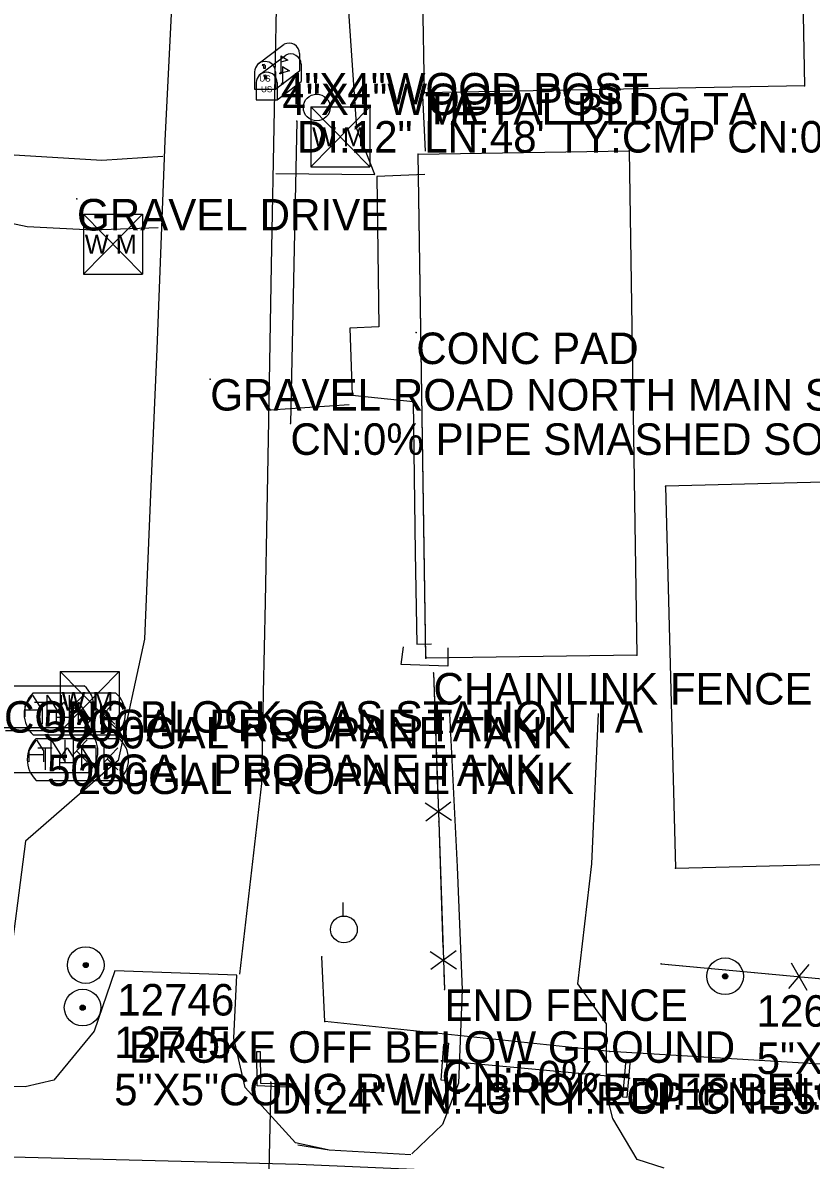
# Model space of a CAD drawing. Extents: x 1050807 to 1053552, y 395828 to 398415.
# Drawn here: x 1051611.7 to 1051736.8, y 398091.9 to 398272.3 of the extents above; entities that cross this region are included whole.
import ezdxf

# ---------------------------------------------------------------- set-up
doc = ezdxf.new("R2010")
doc.units = 0
for name, color, linetype in [('S_BUILDING', 7, 'Continuous'), ('S_BUILDING_ANNOT', 7, 'Continuous'), ('S_CROSS_DRAIN', 7, 'Continuous'), ('S_CROSS_DRAIN_ANNOT', 7, 'Continuous'), ('S_DRG_PT_SYM', 7, 'Continuous'), ('S_DRIVEWAY', 7, 'Continuous'), ('S_EDGE_CONCRETE', 7, 'Continuous'), ('S_EDGE_PAVEMENT', 7, 'Continuous'), ('S_FENCE', 7, 'Continuous'), ('S_FENCE_ANNOT', 7, 'Continuous'), ('S_GRAVEL_ROAD', 7, 'Continuous'), ('S_HEADWALL', 7, 'Continuous'), ('S_IRON_PIN', 7, 'Continuous'), ('S_IRON_PIN_ANNOT', 7, 'Continuous'), ('S_MAILBOX', 7, 'Continuous'), ('S_MAILBOX_ANNOT', 7, 'Continuous'), ('S_MSC_PT_SYM', 7, 'Continuous'), ('S_SHOULDER', 7, 'Continuous'), ('S_STR_PT_SYM', 7, 'Continuous'), ('S_SURVEY_TEXT_ANNOT', 7, 'Continuous'), ('S_TANK', 7, 'Continuous'), ('S_TANK_ANNOT', 7, 'Continuous'), ('S_UTILITY_POLE', 7, 'Continuous'), ('S_UTL_PT_SYM', 7, 'Continuous'), ('S_WATER_UTILITIES', 7, 'Continuous')]:
    doc.layers.add(name, color=color, linetype=linetype)

msp = doc.modelspace()

# ---------------------------------------------------------------- linework, layer by layer
at = {"layer": 'S_BUILDING'}
for p, q in [((1051734.78, 398312.8), (1051735.73, 398262.3)), ((1051675.44, 398261.14), (1051674.48, 398311.66)), ((1051675.44, 398261.16), (1051674.48, 398311.66)), ((1051735.73, 398262.3), (1051675.44, 398261.16)), ((1051674.4, 398251.46), (1051707.9, 398251.97)), ((1051675.63, 398171.71), (1051674.4, 398251.46)), ((1051675.63, 398171.47), (1051674.4, 398251.46)), ((1051707.9, 398251.97), (1051709.13, 398171.98)), ((1051754.28, 398199.8), (1051713.69, 398198.75)), ((1051713.69, 398198.75), (1051715.26, 398138.16)), ((1051709.13, 398171.98), (1051675.63, 398171.47)), ((1051715.26, 398138.16), (1051775.84, 398139.73))]:
    msp.add_line(p, q, dxfattribs=at)
at = {"layer": 'S_CROSS_DRAIN'}
for p, q in [((1051655.17, 398256.69), (1051654.14, 398208.74)), ((1051707.99, 398104.89), (1051678.15, 398107.62)), ((1051651.04, 398104.23), (1051650.09, 398061.31))]:
    msp.add_line(p, q, dxfattribs=at)
at = {"layer": 'S_DRG_PT_SYM'}
for points in [[(1051655.17, 398256.69), (1051655.17, 398256.74), (1051655.17, 398256.69), (1051655.12, 398256.69), (1051655.17, 398256.69), (1051655.17, 398256.64), (1051655.17, 398256.69), (1051655.22, 398256.69)], [(1051654.14, 398208.74), (1051654.14, 398208.79), (1051654.14, 398208.74), (1051654.09, 398208.74), (1051654.14, 398208.74), (1051654.14, 398208.69), (1051654.14, 398208.74), (1051654.19, 398208.74)], [(1051678.15, 398107.62), (1051678.15, 398107.67), (1051678.15, 398107.62), (1051678.1, 398107.62), (1051678.15, 398107.62), (1051678.15, 398107.57), (1051678.15, 398107.62), (1051678.2, 398107.62)], [(1051651.04, 398104.23), (1051651.04, 398104.28), (1051651.04, 398104.23), (1051650.99, 398104.23), (1051651.04, 398104.23), (1051651.04, 398104.18), (1051651.04, 398104.23), (1051651.09, 398104.23)], [(1051707.99, 398104.89), (1051707.99, 398104.94), (1051707.99, 398104.89), (1051707.94, 398104.89), (1051707.99, 398104.89), (1051707.99, 398104.84), (1051707.99, 398104.89), (1051708.04, 398104.89)]]:
    msp.add_lwpolyline(points, dxfattribs=at)
at = {"layer": 'S_DRIVEWAY'}
for points in [[(1051633.9, 398251.06), (1051624.2, 398250.45), (1051611.13, 398251.24), (1051598.06, 398252.03)], [(1051600.84, 398242.41), (1051612.38, 398239.95), (1051622.75, 398239.41), (1051633.14, 398239.78)]]:
    msp.add_lwpolyline(points, dxfattribs=at)
at = {"layer": 'S_EDGE_CONCRETE'}
for points in [[(1051675.5, 398248.23), (1051667.87, 398247.87), (1051668.16, 398224.07), (1051663.57, 398223.86), (1051663.97, 398213.21), (1051673.61, 398212.18), (1051673.95, 398188.26), (1051674.19, 398173.7), (1051676.55, 398173.76)], [(1051679.11, 398173.15), (1051679.15, 398170.23), (1051671.75, 398170.51), (1051672.12, 398173.28)]]:
    msp.add_lwpolyline(points, dxfattribs=at)
at = {"layer": 'S_EDGE_PAVEMENT'}
for points in [[(1051679.39, 398162.7), (1051680.64, 398138.4), (1051681.41, 398118.88), (1051680.81, 398104.07), (1051678.3, 398097.51), (1051673.44, 398092.89)], [(1051713.48, 398090.6), (1051709.19, 398091.98), (1051705.31, 398098.47), (1051704.3, 398102.36), (1051704.31, 398113.47), (1051699.76, 398119.86), (1051701.99, 398138.89), (1051703.06, 398162.71)], [(1051660.07, 398093.51), (1051654.98, 398094.64), (1051646.94, 398103.37), (1051645.14, 398111.23), (1051645.64, 398121.2), (1051626.27, 398121.92), (1051623.02, 398112.31), (1051616.62, 398104.54), (1051612.06, 398103.47), (1051594.68, 398103.64), (1051577.3, 398103.81), (1051557.13, 398104.42)], [(1051831.93, 398069.76), (1051807.96, 398075.33), (1051783.99, 398080.9), (1051771.44, 398082.45), (1051758.89, 398083.99), (1051746.34, 398085.53), (1051733.79, 398087.07), (1051716.6, 398088.19), (1051699.41, 398089.32), (1051677.43, 398090.24), (1051655.45, 398091.16), (1051630.63, 398091.8), (1051605.81, 398092.43), (1051581.35, 398093.1), (1051556.88, 398093.77)]]:
    msp.add_lwpolyline(points, dxfattribs=at)
at = {"layer": 'S_FENCE'}
for p, q in [((1051676.85, 398169.14), (1051677.68, 398145.54)), ((1051675.53, 398148.53), (1051679.72, 398145.8)), ((1051675.53, 398148.53), (1051679.72, 398145.8)), ((1051679.62, 398148.67), (1051675.63, 398145.66)), ((1051679.62, 398148.67), (1051675.63, 398145.66)), ((1051677.68, 398145.54), (1051678.59, 398118.96)), ((1051676.34, 398124.95), (1051680.53, 398122.23)), ((1051676.34, 398124.95), (1051680.53, 398122.23)), ((1051680.43, 398125.09), (1051676.43, 398122.09)), ((1051680.43, 398125.09), (1051676.43, 398122.09)), ((1051712.99, 398123.01), (1051762.29, 398118.45)), ((1051733.65, 398123.15), (1051736.13, 398118.81)), ((1051733.65, 398123.15), (1051736.13, 398118.81)), ((1051733.28, 398119.07), (1051736.51, 398122.89)), ((1051733.28, 398119.07), (1051736.51, 398122.89))]:
    msp.add_line(p, q, dxfattribs=at)
for points in [[(1051676.85, 398169.14), (1051677.55, 398149.16)], [(1051676.85, 398169.14), (1051677.55, 398149.16)], [(1051677.68, 398145.54), (1051678.36, 398125.59)], [(1051677.68, 398145.54), (1051678.36, 398125.59)], [(1051712.99, 398123.01), (1051732.9, 398121.17)], [(1051712.99, 398123.01), (1051732.9, 398121.17)], [(1051678.5, 398121.6), (1051678.59, 398118.96)], [(1051678.5, 398121.6), (1051678.59, 398118.96)]]:
    msp.add_lwpolyline(points, dxfattribs=at)
at = {"layer": 'S_GRAVEL_ROAD'}
for points in [[(1051646.11, 398121.35), (1051647.87, 398136.49), (1051649.63, 398151.62), (1051649.9, 398166.01), (1051650.17, 398180.39), (1051650.44, 398194.78), (1051650.71, 398209.17), (1051651.17, 398233.83), (1051651.63, 398258.49), (1051652.11, 398282.74), (1051652.58, 398307), (1051652.86, 398330.58), (1051653.15, 398354.17), (1051652.43, 398372.13), (1051651.71, 398390.09)], [(1051596, 398378.84), (1051614.53, 398374.86), (1051630.13, 398364.4), (1051635.87, 398350.62), (1051635.97, 398336.92), (1051636.08, 398323.21), (1051636.19, 398309.51), (1051636.29, 398295.81), (1051635.27, 398274.7), (1051634.24, 398253.59), (1051633.6, 398237.04), (1051632.96, 398220.48), (1051631.96, 398197.51), (1051630.97, 398174.53), (1051626.82, 398155.24), (1051612.08, 398142.48), (1051609.17, 398119.93), (1051608.83, 398103.64)], [(1051651.83, 398248.35), (1051667.57, 398248.22), (1051664.68, 398255.48), (1051663.69, 398270.22), (1051662.7, 398284.95), (1051663.01, 398308.7), (1051661.12, 398315.25), (1051655.29, 398310.44), (1051652.69, 398306.96)], [(1051675.09, 398260.74), (1051675.56, 398251.91)], [(1051663.48, 398211.65), (1051650.98, 398210.85)]]:
    msp.add_lwpolyline(points, dxfattribs=at)
at = {"layer": 'S_HEADWALL'}
for points in [[(1051678.59, 398110.46), (1051679.23, 398110.44), (1051678.71, 398104.52), (1051678.08, 398104.58), (1051678.48, 398110.26)], [(1051654.95, 398104.01), (1051654.88, 398103.41), (1051648.86, 398103.66), (1051648.84, 398109.11), (1051649.37, 398109.11), (1051649.42, 398104.1), (1051654.79, 398103.96)], [(1051707.52, 398101.81), (1051706.93, 398101.87), (1051707.42, 398107.81), (1051708.07, 398107.76), (1051707.54, 398101.81)]]:
    msp.add_lwpolyline(points, dxfattribs=at)
at = {"layer": 'S_IRON_PIN'}
for centre, radius in [((1051621.66, 398122.81), 2.91), ((1051621.66, 398122.81), 0.411), ((1051621.66, 398122.81), 0.262), ((1051621.66, 398122.81), 0.212), ((1051723.14, 398121.03), 2.91), ((1051621.66, 398122.81), 0.145), ((1051621.66, 398122.81), 0.0822), ((1051621.66, 398122.81), 0.0581), ((1051723.14, 398121.03), 0.411), ((1051723.14, 398121.03), 0.262), ((1051723.14, 398121.03), 0.212), ((1051723.14, 398121.03), 0.145), ((1051723.14, 398121.03), 0.0822), ((1051723.14, 398121.03), 0.0581), ((1051621.17, 398116.06), 2.91), ((1051621.17, 398116.06), 0.411), ((1051621.17, 398116.06), 0.262), ((1051621.17, 398116.06), 0.212), ((1051621.17, 398116.06), 0.145), ((1051621.17, 398116.06), 0.0822), ((1051621.17, 398116.06), 0.0581)]:
    msp.add_circle(centre, radius, dxfattribs=at)
at = {"layer": 'S_MAILBOX'}
for p, q in [((1051649.01, 398265.75), (1051653.15, 398268.86)), ((1051655.58, 398267.39), (1051655.58, 398264.67)), ((1051649.27, 398264.05), (1051653.4, 398267.16)), ((1051652.63, 398267.04), (1051652.63, 398264.32)), ((1051655.83, 398265.69), (1051655.83, 398262.97)), ((1051648.46, 398264.48), (1051648.46, 398261.76)), ((1051651.78, 398261.76), (1051655.58, 398264.67)), ((1051651.78, 398264.48), (1051651.78, 398261.76)), ((1051652.88, 398265.34), (1051652.88, 398262.63)), ((1051648.71, 398262.78), (1051648.71, 398260.07)), ((1051652.04, 398260.07), (1051655.83, 398262.97)), ((1051652.04, 398262.78), (1051652.04, 398260.07)), ((1051648.46, 398261.76), (1051651.78, 398261.76)), ((1051648.71, 398260.07), (1051652.04, 398260.07))]:
    msp.add_line(p, q, dxfattribs=at)
for points in [[(1051649.64, 398265.59), (1051649.87, 398265.45), (1051649.87, 398265.07), (1051650.17, 398265.07), (1051650.17, 398265.43), (1051649.98, 398265.67), (1051649.64, 398265.62)], [(1051652.63, 398267.04), (1051653.74, 398266.37), (1051652.63, 398266.03)], [(1051649.9, 398263.9), (1051650.12, 398263.76), (1051650.12, 398263.37), (1051650.42, 398263.37), (1051650.42, 398263.73), (1051650.23, 398263.98), (1051649.9, 398263.92)], [(1051652.88, 398265.34), (1051653.99, 398264.68), (1051652.88, 398264.33)]]:
    msp.add_lwpolyline(points, dxfattribs=at)
for centre, end in [((1051653.92, 398267.39), 117.5718), ((1051654.17, 398265.69), 117.5718), ((1051650.12, 398264.48), 180), ((1051650.38, 398262.78), 180)]:
    msp.add_arc(centre, 1.66, 0, end, dxfattribs=at)
for centre in [(1051652.63, 398264.32), (1051652.88, 398262.63)]:
    msp.add_ellipse(centre, major_axis=(0.145, 0.132), ratio=0.564646, dxfattribs=at)
at = {"layer": 'S_MSC_PT_SYM'}
for points in [[(1051620.27, 398244.33), (1051620.27, 398244.38), (1051620.27, 398244.33), (1051620.22, 398244.33), (1051620.27, 398244.33), (1051620.27, 398244.28), (1051620.27, 398244.33), (1051620.32, 398244.33)], [(1051674.13, 398223.14), (1051674.13, 398223.19), (1051674.13, 398223.14), (1051674.08, 398223.14), (1051674.13, 398223.14), (1051674.13, 398223.09), (1051674.13, 398223.14), (1051674.18, 398223.14)], [(1051641.42, 398215.77), (1051641.42, 398215.82), (1051641.42, 398215.77), (1051641.37, 398215.77), (1051641.42, 398215.77), (1051641.42, 398215.72), (1051641.42, 398215.77), (1051641.47, 398215.77)], [(1051676.85, 398169.14), (1051676.85, 398169.19), (1051676.85, 398169.14), (1051676.8, 398169.14), (1051676.85, 398169.14), (1051676.85, 398169.09), (1051676.85, 398169.14), (1051676.9, 398169.14)], [(1051677.68, 398145.54), (1051677.68, 398145.59), (1051677.68, 398145.54), (1051677.63, 398145.54), (1051677.68, 398145.54), (1051677.68, 398145.49), (1051677.68, 398145.54), (1051677.73, 398145.54)], [(1051712.99, 398123.01), (1051712.99, 398123.06), (1051712.99, 398123.01), (1051712.94, 398123.01), (1051712.99, 398123.01), (1051712.99, 398122.96), (1051712.99, 398123.01), (1051713.04, 398123.01)], [(1051678.59, 398118.96), (1051678.59, 398119.01), (1051678.59, 398118.96), (1051678.54, 398118.96), (1051678.59, 398118.96), (1051678.59, 398118.91), (1051678.59, 398118.96), (1051678.64, 398118.96)]]:
    msp.add_lwpolyline(points, dxfattribs=at)
at = {"layer": 'S_SHOULDER'}
msp.add_lwpolyline([(1051673.26, 398092.7), (1051660.28, 398093.46), (1051655.32, 398094.22)], dxfattribs=at)
at = {"layer": 'S_STR_PT_SYM'}
for points in [[(1051735.73, 398262.3), (1051735.73, 398262.35), (1051735.73, 398262.3), (1051735.68, 398262.3), (1051735.73, 398262.3), (1051735.73, 398262.25), (1051735.73, 398262.3), (1051735.78, 398262.3)], [(1051675.44, 398261.16), (1051675.44, 398261.21), (1051675.44, 398261.16), (1051675.39, 398261.16), (1051675.44, 398261.16), (1051675.44, 398261.11), (1051675.44, 398261.16), (1051675.49, 398261.16)], [(1051675.44, 398261.14), (1051675.44, 398261.19), (1051675.44, 398261.14), (1051675.39, 398261.14), (1051675.44, 398261.14), (1051675.44, 398261.09), (1051675.44, 398261.14), (1051675.49, 398261.14)], [(1051674.4, 398251.46), (1051674.4, 398251.51), (1051674.4, 398251.46), (1051674.35, 398251.46), (1051674.4, 398251.46), (1051674.4, 398251.41), (1051674.4, 398251.46), (1051674.45, 398251.46)], [(1051674.4, 398251.46), (1051674.4, 398251.51), (1051674.4, 398251.46), (1051674.35, 398251.46), (1051674.4, 398251.46), (1051674.4, 398251.41), (1051674.4, 398251.46), (1051674.45, 398251.46)], [(1051707.9, 398251.97), (1051707.9, 398252.02), (1051707.9, 398251.97), (1051707.85, 398251.97), (1051707.9, 398251.97), (1051707.9, 398251.92), (1051707.9, 398251.97), (1051707.95, 398251.97)], [(1051713.69, 398198.75), (1051713.69, 398198.8), (1051713.69, 398198.75), (1051713.64, 398198.75), (1051713.69, 398198.75), (1051713.69, 398198.7), (1051713.69, 398198.75), (1051713.74, 398198.75)], [(1051675.63, 398171.71), (1051675.63, 398171.76), (1051675.63, 398171.71), (1051675.58, 398171.71), (1051675.63, 398171.71), (1051675.63, 398171.66), (1051675.63, 398171.71), (1051675.68, 398171.71)], [(1051709.13, 398171.98), (1051709.13, 398172.03), (1051709.13, 398171.98), (1051709.08, 398171.98), (1051709.13, 398171.98), (1051709.13, 398171.93), (1051709.13, 398171.98), (1051709.18, 398171.98)], [(1051675.63, 398171.47), (1051675.63, 398171.52), (1051675.63, 398171.47), (1051675.58, 398171.47), (1051675.63, 398171.47), (1051675.63, 398171.42), (1051675.63, 398171.47), (1051675.68, 398171.47)], [(1051715.26, 398138.16), (1051715.26, 398138.21), (1051715.26, 398138.16), (1051715.21, 398138.16), (1051715.26, 398138.16), (1051715.26, 398138.11), (1051715.26, 398138.16), (1051715.31, 398138.16)]]:
    msp.add_lwpolyline(points, dxfattribs=at)
at = {"layer": 'S_TANK'}
for p, q in [((1051608.3, 398167.13), (1051621.41, 398167.13)), ((1051612.05, 398163.9), (1051613.21, 398165.64)), ((1051613.21, 398165.64), (1051614.31, 398163.9)), ((1051613.29, 398165.98), (1051626.4, 398165.98)), ((1051613.55, 398164.49), (1051615.81, 398164.49)), ((1051614.72, 398164.49), (1051614.72, 398161)), ((1051615.54, 398162.16), (1051615.54, 398165.64)), ((1051615.54, 398165.64), (1051617.8, 398162.16)), ((1051617.04, 398162.75), (1051618.2, 398164.49)), ((1051617.8, 398162.16), (1051617.8, 398165.64)), ((1051618.2, 398164.49), (1051619.3, 398162.75)), ((1051619.02, 398165.64), (1051619.02, 398162.16)), ((1051619.02, 398163.32), (1051621.28, 398165.64)), ((1051620.53, 398161), (1051620.53, 398164.49)), ((1051620.53, 398164.49), (1051622.79, 398161)), ((1051622.79, 398161), (1051622.79, 398164.49)), ((1051624.02, 398164.49), (1051624.02, 398161)), ((1051624.02, 398162.17), (1051626.28, 398164.49)), ((1051612.05, 398162.16), (1051612.05, 398163.9)), ((1051614.31, 398163.25), (1051612.05, 398163.25)), ((1051614.31, 398163.9), (1051614.31, 398162.16)), ((1051617.04, 398161), (1051617.04, 398162.75)), ((1051619.3, 398162.75), (1051619.3, 398161)), ((1051619.6, 398163.84), (1051621.28, 398162.16)), ((1051624.6, 398162.68), (1051626.28, 398161)), ((1051619.3, 398162.1), (1051617.04, 398162.1)), ((1051608.3, 398160.48), (1051621.41, 398160.48)), ((1051608.93, 398160.02), (1051622.04, 398160.02)), ((1051613.29, 398159.33), (1051626.4, 398159.33)), ((1051612.67, 398156.79), (1051613.84, 398158.53)), ((1051613.8, 398158.75), (1051626.91, 398158.75)), ((1051613.84, 398158.53), (1051614.94, 398156.79)), ((1051614.06, 398157.27), (1051616.32, 398157.27)), ((1051615.22, 398157.27), (1051615.22, 398153.78)), ((1051616.16, 398155.05), (1051616.16, 398158.53)), ((1051616.16, 398158.53), (1051618.42, 398155.05)), ((1051617.55, 398155.52), (1051618.71, 398157.27)), ((1051618.42, 398155.05), (1051618.42, 398158.53)), ((1051618.71, 398157.27), (1051619.81, 398155.52)), ((1051619.65, 398158.53), (1051619.65, 398155.05)), ((1051619.65, 398156.21), (1051621.91, 398158.53)), ((1051621.03, 398153.78), (1051621.03, 398157.27)), ((1051621.03, 398157.27), (1051623.29, 398153.78)), ((1051623.29, 398153.78), (1051623.29, 398157.27)), ((1051624.52, 398157.27), (1051624.52, 398153.78)), ((1051624.52, 398154.94), (1051626.78, 398157.27)), ((1051612.67, 398155.05), (1051612.67, 398156.79)), ((1051614.94, 398156.14), (1051612.67, 398156.14)), ((1051614.94, 398156.79), (1051614.94, 398155.05)), ((1051617.55, 398153.78), (1051617.55, 398155.52)), ((1051619.81, 398155.52), (1051619.81, 398153.78)), ((1051620.23, 398156.73), (1051621.91, 398155.05)), ((1051619.81, 398154.88), (1051617.55, 398154.88)), ((1051625.1, 398155.46), (1051626.78, 398153.78)), ((1051608.93, 398153.37), (1051622.04, 398153.37)), ((1051613.8, 398152.1), (1051626.91, 398152.1))]:
    msp.add_line(p, q, dxfattribs=at)
for centre, radius, start, end in [((1051618.62, 398163.8), 4.34, 309.9965, 50.0035), ((1051616.48, 398162.65), 4.6, 133.7339, 226.2661), ((1051623.61, 398162.65), 4.34, 309.9965, 50.0035), ((1051619.25, 398156.69), 4.34, 309.9965, 50.0035), ((1051616.98, 398155.43), 4.6, 133.7339, 226.2661), ((1051624.12, 398155.43), 4.34, 309.9965, 50.0035)]:
    msp.add_arc(centre, radius, start, end, dxfattribs=at)
at = {"layer": 'S_UTILITY_POLE'}
for p, q in [((1051658.2, 398260.98), (1051658.2, 398263.09)), ((1051662.51, 398130.6), (1051662.51, 398132.71))]:
    msp.add_line(p, q, dxfattribs=at)
for centre in [(1051658.33, 398258.84), (1051662.63, 398128.46)]:
    msp.add_circle(centre, 2.13, dxfattribs=at)
at = {"layer": 'S_UTL_PT_SYM'}
for points in [[(1051659.11, 398124.12), (1051659.11, 398124.17), (1051659.11, 398124.12), (1051659.06, 398124.12), (1051659.11, 398124.12), (1051659.11, 398124.07), (1051659.11, 398124.12), (1051659.16, 398124.12)], [(1051659.62, 398113.85), (1051659.62, 398113.9), (1051659.62, 398113.85), (1051659.57, 398113.85), (1051659.62, 398113.85), (1051659.62, 398113.8), (1051659.62, 398113.85), (1051659.67, 398113.85)], [(1051704.85, 398109.11), (1051704.85, 398109.16), (1051704.85, 398109.11), (1051704.8, 398109.11), (1051704.85, 398109.11), (1051704.85, 398109.06), (1051704.85, 398109.11), (1051704.9, 398109.11)]]:
    msp.add_lwpolyline(points, dxfattribs=at)
at = {"layer": 'S_WATER_UTILITIES'}
for p, q in [((1051657.39, 398258.92), (1051666.73, 398258.92)), ((1051657.39, 398258.92), (1051657.39, 398249.42)), ((1051657.39, 398258.92), (1051666.73, 398249.42)), ((1051666.73, 398258.92), (1051657.39, 398249.42)), ((1051666.73, 398258.92), (1051666.73, 398249.42)), ((1051657.39, 398249.42), (1051666.73, 398249.42)), ((1051621.31, 398241.9), (1051630.65, 398241.9)), ((1051621.31, 398241.9), (1051621.31, 398232.41)), ((1051621.31, 398241.9), (1051630.65, 398232.41)), ((1051630.65, 398241.9), (1051621.31, 398232.41)), ((1051630.65, 398241.9), (1051630.65, 398232.41)), ((1051621.31, 398232.41), (1051630.65, 398232.41)), ((1051617.62, 398169.37), (1051626.96, 398169.37)), ((1051617.62, 398169.37), (1051617.62, 398159.88)), ((1051617.62, 398169.37), (1051626.96, 398159.88)), ((1051626.96, 398169.37), (1051617.62, 398159.88)), ((1051626.96, 398169.37), (1051626.96, 398159.88)), ((1051617.62, 398159.88), (1051626.96, 398159.88)), ((1051659.62, 398113.85), (1051659.11, 398124.12)), ((1051704.85, 398109.11), (1051659.62, 398113.85)), ((1051741.82, 398106.87), (1051704.85, 398109.11))]:
    msp.add_line(p, q, dxfattribs=at)

# ---------------------------------------------------------------- texts
at = {"layer": 'S_BUILDING_ANNOT'}
for s, p in [('TA', (1051675.44, 398256.16)), ('METAL BLDG TA', (1051675.44, 398256.14)), ('CONC BLOCK GAS STATION TA', (1051608.69, 398159.67))]:
    msp.add_text(s, height=5, dxfattribs=at).set_placement(p)
at = {"layer": 'S_CROSS_DRAIN_ANNOT'}
for s, p in [('DI:12" LN:48\' TY:CMP CN:0%', (1051655.17, 398251.69)), ('CN:0% PIPE SMASHED SOUTH END', (1051654.14, 398203.74)), ('CN:50%', (1051678.15, 398102.62)), ('DI:18" LN:30\' TY:CMP CN:40%', (1051707.99, 398099.89)), ('DI:24" LN:43\' TY:RCP CN:55%', (1051651.04, 398099.23))]:
    msp.add_text(s, height=5, dxfattribs=at).set_placement(p)
at = {"layer": 'S_FENCE_ANNOT'}
for s, p in [('CHAINLINK FENCE', (1051676.85, 398164.14)), ('END FENCE', (1051678.59, 398113.96))]:
    msp.add_text(s, height=5, dxfattribs=at).set_placement(p)
at = {"layer": 'S_IRON_PIN_ANNOT'}
for s, p in [('12746', (1051626.66, 398114.81)), ('12615', (1051728.14, 398113.03)), ('12745', (1051626.17, 398108.06)), (' BROKE OFF BELOW GROUND', (1051626.66, 398107.31)), ('5"X5"CONC RWM', (1051728.14, 398105.53)), ('5"X5"CONC RWM  BROKE OFF BELOW GROUND', (1051626.17, 398100.56))]:
    msp.add_text(s, height=5, dxfattribs=at).set_placement(p)
at = {"layer": 'S_MAILBOX'}
for p in [(1051649.22, 398262.96), (1051649.48, 398261.26)]:
    msp.add_text('US', height=0.96, dxfattribs=at).set_placement(p)
at = {"layer": 'S_MAILBOX_ANNOT'}
for p in [(1051652.63, 398259.32), (1051652.88, 398257.63)]:
    msp.add_text('4"X4"WOOD POST', height=5, dxfattribs=at).set_placement(p)
at = {"layer": 'S_SURVEY_TEXT_ANNOT'}
for s, p in [('GRAVEL DRIVE', (1051620.27, 398239.33)), ('CONC PAD', (1051674.13, 398218.14)), ('GRAVEL ROAD NORTH MAIN STREET', (1051641.42, 398210.77))]:
    msp.add_text(s, height=5, dxfattribs=at).set_placement(p)
at = {"layer": 'S_TANK_ANNOT'}
for s, p in [('500GAL PROPANE TANK', (1051614.89, 398158.32)), ('250GAL PROPANE TANK', (1051619.88, 398157.17)), ('500GAL PROPANE TANK', (1051615.52, 398151.21)), ('250GAL PROPANE TANK', (1051620.39, 398149.94))]:
    msp.add_text(s, height=5, dxfattribs=at).set_placement(p)
at = {"layer": 'S_WATER_UTILITIES'}
for p in [(1051657.59, 398252.68), (1051621.51, 398235.67), (1051617.82, 398163.14)]:
    msp.add_text('W M', height=3, dxfattribs=at).set_placement(p)

doc.saveas('drawing.dxf')
